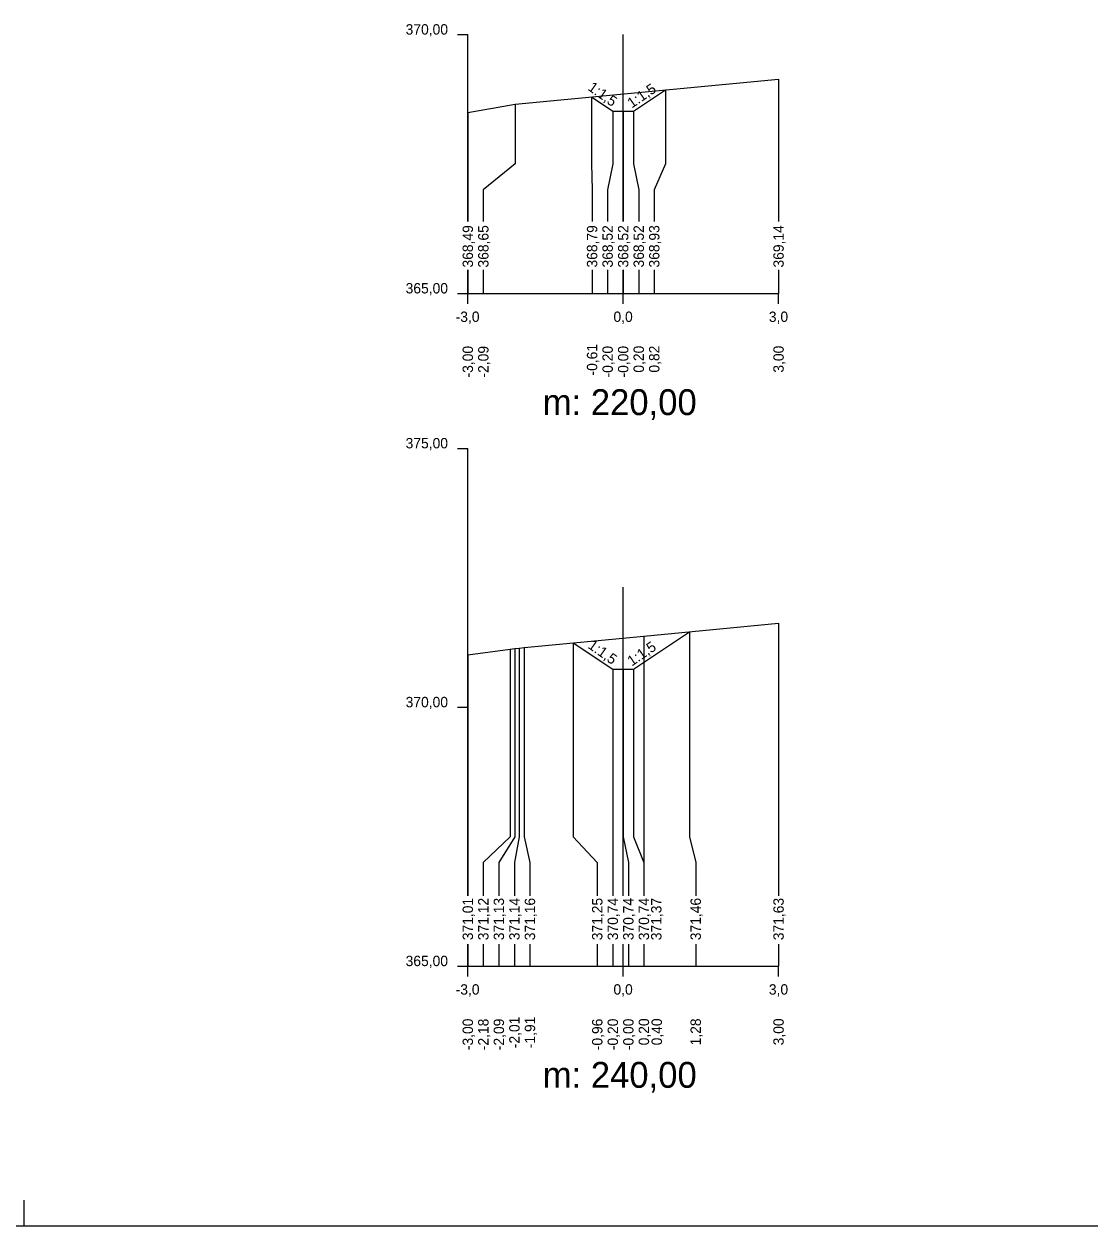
# Model space of a CAD drawing. Extents: x -497367.2 to -497283.2, y -1136708.7 to -1136649.3.
# Drawn here: x -497325.24 to -497304.66, y -1136708.74 to -1136685.52 of the extents above; entities that cross this region are included whole.
import ezdxf

# ---------------------------------------------------------------- set-up
doc = ezdxf.new("R2010")
doc.units = 0
for name, color, linetype in [('11', 7, 'Continuous'), ('16', 7, 'Continuous'), ('21', 7, 'Continuous'), ('28', 7, 'Continuous'), ('59', 7, 'Continuous'), ('8', 7, 'Continuous'), ('Vrstva 63', 7, 'Continuous')]:
    doc.layers.add(name, color=color, linetype=linetype)

msp = doc.modelspace()

# ---------------------------------------------------------------- linework, layer by layer
for points in [[(-497316.671, -1136687.236), (-497315.757, -1136687.075), (-497310.671, -1136686.588)], [(-497314.281, -1136686.934), (-497313.871, -1136687.207), (-497313.671, -1136687.207), (-497313.471, -1136687.207), (-497312.856, -1136686.797)], [(-497313.871, -1136687.208), (-497313.871, -1136687.207), (-497313.871, -1136687.206)], [(-497313.471, -1136687.208), (-497313.471, -1136687.207), (-497313.471, -1136687.206)], [(-497316.671, -1136697.71), (-497315.855, -1136697.596), (-497315.764, -1136697.587), (-497315.679, -1136697.58), (-497315.582, -1136697.564), (-497313.275, -1136697.347), (-497310.671, -1136697.095)], [(-497314.634, -1136697.475), (-497313.871, -1136697.984), (-497313.671, -1136697.983), (-497313.471, -1136697.984), (-497312.387, -1136697.261)], [(-497313.871, -1136697.985), (-497313.871, -1136697.984), (-497313.871, -1136697.982)], [(-497313.471, -1136697.985), (-497313.471, -1136697.984), (-497313.471, -1136697.982)]]:
    msp.add_lwpolyline(points)
at = {"layer": '11'}
for points in [[(-497310.671, -1136686.588), (-497310.671, -1136688.228), (-497310.671, -1136688.728), (-497310.671, -1136689.336)], [(-497312.856, -1136686.797), (-497312.856, -1136688.228), (-497313.071, -1136688.728), (-497313.071, -1136689.336)], [(-497315.757, -1136687.075), (-497315.757, -1136688.228), (-497316.371, -1136688.728), (-497316.371, -1136689.336)], [(-497314.281, -1136686.934), (-497314.281, -1136688.228), (-497314.271, -1136688.728), (-497314.271, -1136689.336)], [(-497316.671, -1136687.236), (-497316.671, -1136688.228), (-497316.671, -1136688.728), (-497316.671, -1136689.336)], [(-497313.871, -1136687.207), (-497313.871, -1136688.228), (-497313.971, -1136688.728), (-497313.971, -1136689.336)], [(-497313.671, -1136687.207), (-497313.671, -1136688.228), (-497313.671, -1136688.728), (-497313.671, -1136689.336)], [(-497313.471, -1136687.207), (-497313.471, -1136688.228), (-497313.371, -1136688.728), (-497313.371, -1136689.336)], [(-497316.671, -1136690.27), (-497316.671, -1136690.728)], [(-497316.371, -1136690.27), (-497316.371, -1136690.728)], [(-497314.271, -1136690.27), (-497314.271, -1136690.728)], [(-497313.971, -1136690.27), (-497313.971, -1136690.728)], [(-497313.671, -1136690.27), (-497313.671, -1136690.728)], [(-497313.371, -1136690.27), (-497313.371, -1136690.728)], [(-497313.071, -1136690.27), (-497313.071, -1136690.728)], [(-497310.671, -1136690.27), (-497310.671, -1136690.728)], [(-497310.671, -1136697.095), (-497310.671, -1136701.22), (-497310.671, -1136701.72), (-497310.671, -1136702.361)], [(-497312.387, -1136697.261), (-497312.387, -1136701.22), (-497312.271, -1136701.72), (-497312.271, -1136702.361)], [(-497315.582, -1136697.564), (-497315.582, -1136701.22), (-497315.471, -1136701.72), (-497315.471, -1136702.361)], [(-497314.634, -1136697.475), (-497314.634, -1136701.22), (-497314.171, -1136701.72), (-497314.171, -1136702.361)], [(-497313.275, -1136697.347), (-497313.275, -1136701.22), (-497313.275, -1136701.72), (-497313.275, -1136702.361)], [(-497316.671, -1136697.71), (-497316.671, -1136701.22), (-497316.671, -1136701.72), (-497316.671, -1136702.361)], [(-497315.855, -1136697.596), (-497315.855, -1136701.22), (-497316.371, -1136701.72), (-497316.371, -1136702.361)], [(-497315.764, -1136697.587), (-497315.764, -1136701.22), (-497316.071, -1136701.72), (-497316.071, -1136702.361)], [(-497315.679, -1136697.58), (-497315.679, -1136701.22), (-497315.771, -1136701.72), (-497315.771, -1136702.361)], [(-497313.871, -1136697.984), (-497313.871, -1136701.22), (-497313.871, -1136701.72), (-497313.871, -1136702.361)], [(-497313.671, -1136697.983), (-497313.671, -1136701.22), (-497313.571, -1136701.72), (-497313.571, -1136702.361)], [(-497313.471, -1136697.984), (-497313.471, -1136701.22), (-497313.271, -1136701.72), (-497313.271, -1136702.361)], [(-497316.671, -1136703.295), (-497316.671, -1136703.72)], [(-497316.371, -1136703.295), (-497316.371, -1136703.72)], [(-497316.071, -1136703.295), (-497316.071, -1136703.72)], [(-497315.771, -1136703.295), (-497315.771, -1136703.72)], [(-497315.471, -1136703.295), (-497315.471, -1136703.72)], [(-497314.171, -1136703.295), (-497314.171, -1136703.72)], [(-497313.871, -1136703.295), (-497313.871, -1136703.72)], [(-497313.571, -1136703.295), (-497313.571, -1136703.72)], [(-497313.275, -1136703.295), (-497313.275, -1136703.72)], [(-497313.271, -1136703.295), (-497313.271, -1136703.72)], [(-497312.271, -1136703.295), (-497312.271, -1136703.72)], [(-497310.671, -1136703.295), (-497310.671, -1136703.72)]]:
    msp.add_lwpolyline(points, dxfattribs=at)
at = {"layer": '16'}
for p, q in [((-497316.671, -1136690.728), (-497310.671, -1136690.728)), ((-497316.671, -1136703.72), (-497310.671, -1136703.72))]:
    msp.add_line(p, q, dxfattribs=at)
for points in [[(-497313.671, -1136687.208), (-497313.671, -1136687.207), (-497313.671, -1136687.206)], [(-497313.671, -1136697.985), (-497313.671, -1136697.983), (-497313.671, -1136697.982)]]:
    msp.add_lwpolyline(points, dxfattribs=at)
at = {"layer": '21'}
for p, q in [((-497316.871, -1136685.728), (-497316.671, -1136685.728)), ((-497316.871, -1136690.728), (-497316.671, -1136690.728)), ((-497316.871, -1136693.72), (-497316.671, -1136693.72)), ((-497316.871, -1136698.72), (-497316.671, -1136698.72)), ((-497316.871, -1136703.72), (-497316.671, -1136703.72))]:
    msp.add_line(p, q, dxfattribs=at)
at = {"layer": '28'}
for p, q in [((-497313.671, -1136689.336), (-497313.671, -1136685.728)), ((-497313.671, -1136690.728), (-497313.671, -1136690.27)), ((-497313.671, -1136702.361), (-497313.671, -1136696.398)), ((-497313.671, -1136703.72), (-497313.671, -1136703.295))]:
    msp.add_line(p, q, dxfattribs=at)
at = {"layer": '59'}
for p, q in [((-497316.671, -1136690.928), (-497316.671, -1136690.728)), ((-497313.671, -1136690.928), (-497313.671, -1136690.728)), ((-497310.671, -1136690.928), (-497310.671, -1136690.728)), ((-497316.671, -1136703.92), (-497316.671, -1136703.72)), ((-497313.671, -1136703.92), (-497313.671, -1136703.72)), ((-497310.671, -1136703.92), (-497310.671, -1136703.72))]:
    msp.add_line(p, q, dxfattribs=at)
at = {"layer": '8'}
for p, q in [((-497316.671, -1136689.336), (-497316.671, -1136685.728)), ((-497316.671, -1136690.728), (-497316.671, -1136690.27)), ((-497316.671, -1136702.361), (-497316.671, -1136693.72)), ((-497316.671, -1136703.72), (-497316.671, -1136703.295))]:
    msp.add_line(p, q, dxfattribs=at)
at = {"layer": 'Vrstva 63'}
for p, q in [((-497325.238, -1136708.738), (-497325.238, -1136708.241)), ((-497367.238, -1136708.736), (-497283.238, -1136708.735))]:
    msp.add_line(p, q, dxfattribs=at)

# ---------------------------------------------------------------- texts
at = {"layer": '16'}
for s, p in [('368,49', (-497316.571, -1136690.228)), ('368,65', (-497316.271, -1136690.228)), ('368,79', (-497314.171, -1136690.228)), ('368,52', (-497313.871, -1136690.228)), ('368,52', (-497313.571, -1136690.228)), ('368,52', (-497313.271, -1136690.228)), ('368,93', (-497312.971, -1136690.228)), ('369,14', (-497310.571, -1136690.228)), ('371,01', (-497316.571, -1136703.22)), ('371,12', (-497316.271, -1136703.22)), ('371,13', (-497315.971, -1136703.22)), ('371,14', (-497315.671, -1136703.22)), ('371,16', (-497315.371, -1136703.22)), ('371,25', (-497314.071, -1136703.22)), ('370,74', (-497313.771, -1136703.22)), ('370,74', (-497313.471, -1136703.22)), ('370,74', (-497313.171, -1136703.22)), ('371,37', (-497312.931, -1136703.22)), ('371,46', (-497312.171, -1136703.22)), ('371,63', (-497310.571, -1136703.22))]:
    msp.add_text(s, height=0.2, rotation=90, dxfattribs=at).set_placement(p)
at = {"layer": '21'}
for s, p in [('370,00', (-497317.871, -1136685.728)), ('365,00', (-497317.871, -1136690.728)), ('-3,0', (-497316.905, -1136691.278)), ('0,0', (-497313.858, -1136691.278)), ('3,0', (-497310.858, -1136691.278)), ('375,00', (-497317.871, -1136693.72)), ('370,00', (-497317.871, -1136698.72)), ('365,00', (-497317.871, -1136703.72)), ('-3,0', (-497316.905, -1136704.27)), ('0,0', (-497313.858, -1136704.27)), ('3,0', (-497310.858, -1136704.27))]:
    msp.add_text(s, height=0.2, dxfattribs=at).set_placement(p)
for rotation, p in [(324.91, (-497314.367, -1136686.789)), (34.4489, (-497313.504, -1136687.159)), (324.91, (-497314.367, -1136697.565)), (34.4489, (-497313.504, -1136697.935))]:
    msp.add_text('1:1,5', height=0.2, rotation=rotation, dxfattribs=at).set_placement(p)
at = {"layer": '28'}
for s, p in [('m: 220,00', (-497315.224, -1136693.078)), ('m: 240,00', (-497315.224, -1136706.07))]:
    msp.add_text(s, height=0.5, dxfattribs=at).set_placement(p)
at = {"layer": '59'}
for s, p in [('-3,00', (-497316.571, -1136692.351)), ('-2,09', (-497316.271, -1136692.352)), ('-0,61', (-497314.171, -1136692.313)), ('-0,20', (-497313.871, -1136692.351)), ('-0,00', (-497313.571, -1136692.351)), ('0,20', (-497313.271, -1136692.258)), ('0,82', (-497312.971, -1136692.257)), ('3,00', (-497310.571, -1136692.258)), ('-3,00', (-497316.571, -1136705.343)), ('-2,18', (-497316.271, -1136705.344)), ('-2,09', (-497315.971, -1136705.344)), ('-2,01', (-497315.671, -1136705.305)), ('-1,91', (-497315.371, -1136705.305)), ('-0,96', (-497314.071, -1136705.344)), ('-0,20', (-497313.771, -1136705.343)), ('-0,00', (-497313.471, -1136705.343)), ('0,20', (-497313.171, -1136705.25)), ('0,40', (-497312.923, -1136705.25)), ('1,28', (-497312.171, -1136705.251)), ('3,00', (-497310.571, -1136705.25))]:
    msp.add_text(s, height=0.2, rotation=90, dxfattribs=at).set_placement(p)

doc.saveas('drawing.dxf')
